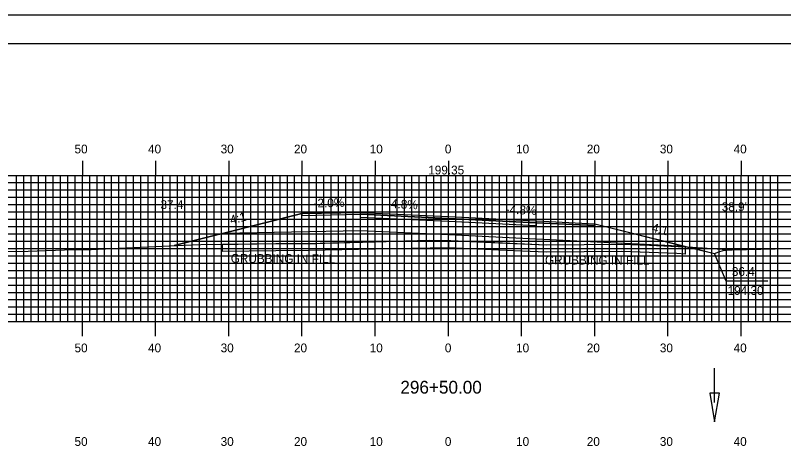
# Model space of a CAD drawing. Extents: x 1814522 to 1814865, y 442591 to 442811.
# Drawn here: x 1814628.4 to 1814733.3, y 442751.2 to 442810.5 of the extents above; entities that cross this region are included whole.
import ezdxf

# ---------------------------------------------------------------- set-up
doc = ezdxf.new("R2010")
doc.units = 0
for name, color, linetype in [('ANNOTATION', 7, 'Continuous'), ('BORDER', 7, 'Continuous'), ('D_Drainage_Ditch_Line', 7, 'Continuous'), ('D_Roadway_Centerline', 7, 'Continuous'), ('D_Roadway_Centerline_Text', 7, 'Continuous'), ('D_Roadway_Edge_Shoulder', 7, 'Continuous'), ('D_Roadway_Edge_TW', 7, 'Continuous'), ('D_Roadway_Pavement', 7, 'Continuous'), ('D_Roadway_SlopeLines', 7, 'Continuous'), ('D_Roadway_SubGrade', 7, 'Continuous'), ('D_Text_Standard', 7, 'Continuous'), ('GRUBBING IN FILL', 7, 'Continuous'), ('H_V ANNOTATION', 7, 'Continuous'), ('MAJOR', 7, 'Continuous'), ('MINOR', 7, 'Continuous'), ('PLOT BOUNDARY', 7, 'Continuous'), ('S_Roadway_Centerline', 7, 'Continuous')]:
    doc.layers.add(name, color=color, linetype=linetype)

msp = doc.modelspace()

# ---------------------------------------------------------------- linework, layer by layer
at = {"layer": 'ANNOTATION'}
msp.add_lwpolyline([(1814731.14, 442774.19), (1814725.44, 442774.19), (1814723.88, 442777.96)], dxfattribs=at)
at = {"layer": 'BORDER'}
msp.add_lwpolyline([(1814537.91, 442596.67), (1814857.91, 442596.67), (1814857.91, 442806.67), (1814537.91, 442806.67)], close=True, dxfattribs=at)
at = {"layer": 'D_Drainage_Ditch_Line'}
msp.add_line((1814723.88, 442757.59), (1814723.88, 442762.29), dxfattribs=at)
msp.add_lwpolyline([(1814724.54, 442758.9), (1814723.23, 442758.9), (1814723.88, 442754.96)], close=True, dxfattribs=at)
at = {"layer": 'D_Roadway_Centerline'}
msp.add_lwpolyline([(1814650.06, 442779.07), (1814655.51, 442780.43), (1814656.64, 442780.71), (1814667.51, 442783.43), (1814675.51, 442783.59), (1814687.51, 442783.02), (1814699.51, 442782.44), (1814707.51, 442782.06), (1814719.88, 442778.96), (1814723.88, 442777.96), (1814724.48, 442778.22), (1814725.07, 442778.39), (1814725.67, 442778.47), (1814726.26, 442778.47)], dxfattribs=at)
at = {"layer": 'D_Roadway_Edge_Shoulder'}
for points in [[(1814675.51, 442783.59), (1814667.51, 442783.43), (1814667.51, 442783.18), (1814675.51, 442783.34)], [(1814699.51, 442782.44), (1814707.51, 442782.06), (1814707.51, 442781.81), (1814699.51, 442782.19)]]:
    msp.add_lwpolyline(points, close=True, dxfattribs=at)
at = {"layer": 'D_Roadway_Edge_TW'}
msp.add_lwpolyline([(1814675.51, 442783.34), (1814675.51, 442783.59), (1814687.51, 442783.02), (1814699.51, 442782.44), (1814699.51, 442782.19), (1814687.51, 442782.77)], close=True, dxfattribs=at)
at = {"layer": 'D_Roadway_Pavement'}
msp.add_lwpolyline([(1814675.51, 442782.92), (1814675.51, 442783.34), (1814687.51, 442782.77), (1814699.51, 442782.19), (1814699.51, 442781.77), (1814687.51, 442782.35)], close=True, dxfattribs=at)
at = {"layer": 'D_Roadway_SlopeLines'}
for points in [[(1814667.51, 442783.43), (1814656.64, 442780.71), (1814655.51, 442780.43), (1814650.06, 442779.07)], [(1814707.51, 442782.06), (1814723.88, 442777.96)], [(1814723.88, 442777.96), (1814724.48, 442778.22), (1814725.07, 442778.39), (1814725.67, 442778.47), (1814726.26, 442778.47)]]:
    msp.add_lwpolyline(points, dxfattribs=at)
at = {"layer": 'D_Roadway_SubGrade'}
msp.add_lwpolyline([(1814675.51, 442781.09), (1814656.64, 442780.71), (1814667.51, 442783.43), (1814667.51, 442783.18), (1814675.51, 442783.34), (1814687.51, 442782.77), (1814699.51, 442782.19), (1814707.51, 442781.81), (1814707.51, 442782.06), (1814719.88, 442778.96), (1814699.51, 442779.94), (1814687.51, 442780.52)], close=True, dxfattribs=at)
at = {"layer": 'GRUBBING IN FILL'}
for points in [[(1814656.64, 442779.25), (1814658.81, 442779.27), (1814663.94, 442779.33), (1814668.89, 442779.37), (1814677.49, 442779.59), (1814684.98, 442779.79), (1814687.51, 442779.75), (1814687.51, 442778.75), (1814677.51, 442778.59), (1814668.41, 442778.37), (1814663.96, 442778.33), (1814656.64, 442778.25)], [(1814656.64, 442779.25), (1814658.81, 442779.27), (1814663.94, 442779.33), (1814668.89, 442779.37), (1814677.49, 442779.59), (1814684.98, 442779.79), (1814687.51, 442779.75), (1814687.51, 442778.75), (1814677.51, 442778.59), (1814668.41, 442778.37), (1814663.96, 442778.33), (1814656.64, 442778.25)], [(1814687.51, 442779.75), (1814694.37, 442779.44), (1814700.91, 442779.15), (1814706.05, 442779.2), (1814711.2, 442779.26), (1814714.99, 442779.12), (1814719.88, 442778.91), (1814719.88, 442777.9), (1814718.73, 442777.98), (1814714.96, 442778.12), (1814711.19, 442778.26), (1814706.04, 442778.2), (1814700.89, 442778.15), (1814694.35, 442778.44), (1814687.51, 442778.75)], [(1814687.51, 442779.75), (1814694.37, 442779.44), (1814700.91, 442779.15), (1814706.05, 442779.2), (1814711.2, 442779.26), (1814714.99, 442779.12), (1814719.88, 442778.91), (1814719.88, 442777.9), (1814718.73, 442777.98), (1814714.96, 442778.12), (1814711.19, 442778.26), (1814706.04, 442778.2), (1814700.89, 442778.15), (1814694.35, 442778.44), (1814687.51, 442778.75)]]:
    msp.add_lwpolyline(points, close=True, dxfattribs=at)
at = {"layer": 'MAJOR'}
for p, q in [((1814637.51, 442790.67), (1814637.51, 442788.67)), ((1814647.51, 442790.67), (1814647.51, 442788.67)), ((1814657.51, 442790.67), (1814657.51, 442788.67)), ((1814667.51, 442790.67), (1814667.51, 442788.67)), ((1814677.51, 442790.67), (1814677.51, 442788.67)), ((1814687.51, 442790.67), (1814687.51, 442788.67)), ((1814697.51, 442790.67), (1814697.51, 442788.67)), ((1814707.51, 442790.67), (1814707.51, 442788.67)), ((1814717.51, 442790.67), (1814717.51, 442788.67)), ((1814727.51, 442790.67), (1814727.51, 442788.67)), ((1814547.51, 442788.67), (1814827.51, 442788.67)), ((1814547.51, 442788.67), (1814827.51, 442788.67)), ((1814637.51, 442768.67), (1814637.51, 442788.67)), ((1814647.51, 442768.67), (1814647.51, 442788.67)), ((1814657.51, 442768.67), (1814657.51, 442788.67)), ((1814667.51, 442768.67), (1814667.51, 442788.67)), ((1814677.51, 442768.67), (1814677.51, 442788.67)), ((1814687.51, 442768.67), (1814687.51, 442788.67)), ((1814697.51, 442768.67), (1814697.51, 442788.67)), ((1814707.51, 442768.67), (1814707.51, 442788.67)), ((1814717.51, 442768.67), (1814717.51, 442788.67)), ((1814727.51, 442768.67), (1814727.51, 442788.67)), ((1814547.51, 442783.67), (1814827.51, 442783.67)), ((1814547.51, 442778.67), (1814827.51, 442778.67)), ((1814547.51, 442773.67), (1814827.51, 442773.67)), ((1814547.51, 442768.67), (1814827.51, 442768.67)), ((1814547.51, 442768.67), (1814827.51, 442768.67)), ((1814637.51, 442766.66), (1814637.51, 442768.67)), ((1814647.51, 442766.66), (1814647.51, 442768.67)), ((1814657.51, 442766.66), (1814657.51, 442768.67)), ((1814667.51, 442766.66), (1814667.51, 442768.67)), ((1814677.51, 442766.66), (1814677.51, 442768.67)), ((1814687.51, 442766.66), (1814687.51, 442768.67)), ((1814697.51, 442766.66), (1814697.51, 442768.67)), ((1814707.51, 442766.66), (1814707.51, 442768.67)), ((1814717.51, 442766.66), (1814717.51, 442768.67)), ((1814727.51, 442766.66), (1814727.51, 442768.67))]:
    msp.add_line(p, q, dxfattribs=at)
at = {"layer": 'MINOR'}
for p, q in [((1814547.51, 442787.67), (1814827.51, 442787.67)), ((1814628.51, 442768.67), (1814628.51, 442788.67)), ((1814629.51, 442768.67), (1814629.51, 442788.67)), ((1814630.51, 442768.67), (1814630.51, 442788.67)), ((1814631.51, 442768.67), (1814631.51, 442788.67)), ((1814632.51, 442768.67), (1814632.51, 442788.67)), ((1814633.51, 442768.67), (1814633.51, 442788.67)), ((1814634.51, 442768.67), (1814634.51, 442788.67)), ((1814635.51, 442768.67), (1814635.51, 442788.67)), ((1814636.51, 442768.67), (1814636.51, 442788.67)), ((1814638.51, 442768.67), (1814638.51, 442788.67)), ((1814639.51, 442768.67), (1814639.51, 442788.67)), ((1814640.51, 442768.67), (1814640.51, 442788.67)), ((1814641.51, 442768.67), (1814641.51, 442788.67)), ((1814642.51, 442768.67), (1814642.51, 442788.67)), ((1814643.51, 442768.67), (1814643.51, 442788.67)), ((1814644.51, 442768.67), (1814644.51, 442788.67)), ((1814645.51, 442768.67), (1814645.51, 442788.67)), ((1814646.51, 442768.67), (1814646.51, 442788.67)), ((1814648.51, 442768.67), (1814648.51, 442788.67)), ((1814649.51, 442768.67), (1814649.51, 442788.67)), ((1814650.51, 442768.67), (1814650.51, 442788.67)), ((1814651.51, 442768.67), (1814651.51, 442788.67)), ((1814652.51, 442768.67), (1814652.51, 442788.67)), ((1814653.51, 442768.67), (1814653.51, 442788.67)), ((1814654.51, 442768.67), (1814654.51, 442788.67)), ((1814655.51, 442768.67), (1814655.51, 442788.67)), ((1814656.51, 442768.67), (1814656.51, 442788.67)), ((1814658.51, 442768.67), (1814658.51, 442788.67)), ((1814659.51, 442768.67), (1814659.51, 442788.67)), ((1814660.51, 442768.67), (1814660.51, 442788.67)), ((1814661.51, 442768.67), (1814661.51, 442788.67)), ((1814662.51, 442768.67), (1814662.51, 442788.67)), ((1814663.51, 442768.67), (1814663.51, 442788.67)), ((1814664.51, 442768.67), (1814664.51, 442788.67)), ((1814665.51, 442768.67), (1814665.51, 442788.67)), ((1814666.51, 442768.67), (1814666.51, 442788.67)), ((1814668.51, 442768.67), (1814668.51, 442788.67)), ((1814669.51, 442768.67), (1814669.51, 442788.67)), ((1814670.51, 442768.67), (1814670.51, 442788.67)), ((1814671.51, 442768.67), (1814671.51, 442788.67)), ((1814672.51, 442768.67), (1814672.51, 442788.67)), ((1814673.51, 442768.67), (1814673.51, 442788.67)), ((1814674.51, 442768.67), (1814674.51, 442788.67)), ((1814675.51, 442768.67), (1814675.51, 442788.67)), ((1814676.51, 442768.67), (1814676.51, 442788.67)), ((1814678.51, 442768.67), (1814678.51, 442788.67)), ((1814679.51, 442768.67), (1814679.51, 442788.67)), ((1814680.51, 442768.67), (1814680.51, 442788.67)), ((1814681.51, 442768.67), (1814681.51, 442788.67)), ((1814682.51, 442768.67), (1814682.51, 442788.67)), ((1814683.51, 442768.67), (1814683.51, 442788.67)), ((1814684.51, 442768.67), (1814684.51, 442788.67)), ((1814685.51, 442768.67), (1814685.51, 442788.67)), ((1814686.51, 442768.67), (1814686.51, 442788.67)), ((1814688.51, 442768.67), (1814688.51, 442788.67)), ((1814689.51, 442768.67), (1814689.51, 442788.67)), ((1814690.51, 442768.67), (1814690.51, 442788.67)), ((1814691.51, 442768.67), (1814691.51, 442788.67)), ((1814692.51, 442768.67), (1814692.51, 442788.67)), ((1814693.51, 442768.67), (1814693.51, 442788.67)), ((1814694.51, 442768.67), (1814694.51, 442788.67)), ((1814695.51, 442768.67), (1814695.51, 442788.67)), ((1814696.51, 442768.67), (1814696.51, 442788.67)), ((1814698.51, 442768.67), (1814698.51, 442788.67)), ((1814699.51, 442768.67), (1814699.51, 442788.67)), ((1814700.51, 442768.67), (1814700.51, 442788.67)), ((1814701.51, 442768.67), (1814701.51, 442788.67)), ((1814702.51, 442768.67), (1814702.51, 442788.67)), ((1814703.51, 442768.67), (1814703.51, 442788.67)), ((1814704.51, 442768.67), (1814704.51, 442788.67)), ((1814705.51, 442768.67), (1814705.51, 442788.67)), ((1814706.51, 442768.67), (1814706.51, 442788.67)), ((1814708.51, 442768.67), (1814708.51, 442788.67)), ((1814709.51, 442768.67), (1814709.51, 442788.67)), ((1814710.51, 442768.67), (1814710.51, 442788.67)), ((1814711.51, 442768.67), (1814711.51, 442788.67)), ((1814712.51, 442768.67), (1814712.51, 442788.67)), ((1814713.51, 442768.67), (1814713.51, 442788.67)), ((1814714.51, 442768.67), (1814714.51, 442788.67)), ((1814715.51, 442768.67), (1814715.51, 442788.67)), ((1814716.51, 442768.67), (1814716.51, 442788.67)), ((1814718.51, 442768.67), (1814718.51, 442788.67)), ((1814719.51, 442768.67), (1814719.51, 442788.67)), ((1814720.51, 442768.67), (1814720.51, 442788.67)), ((1814721.51, 442768.67), (1814721.51, 442788.67)), ((1814722.51, 442768.67), (1814722.51, 442788.67)), ((1814723.51, 442768.67), (1814723.51, 442788.67)), ((1814724.51, 442768.67), (1814724.51, 442788.67)), ((1814725.51, 442768.67), (1814725.51, 442788.67)), ((1814726.51, 442768.67), (1814726.51, 442788.67)), ((1814728.51, 442768.67), (1814728.51, 442788.67)), ((1814729.51, 442768.67), (1814729.51, 442788.67)), ((1814730.51, 442768.67), (1814730.51, 442788.67)), ((1814731.51, 442768.67), (1814731.51, 442788.67)), ((1814732.51, 442768.67), (1814732.51, 442788.67)), ((1814547.51, 442786.67), (1814827.51, 442786.67)), ((1814547.51, 442785.67), (1814827.51, 442785.67)), ((1814547.51, 442784.67), (1814827.51, 442784.67)), ((1814547.51, 442782.67), (1814827.51, 442782.67)), ((1814547.51, 442781.67), (1814827.51, 442781.67)), ((1814547.51, 442780.67), (1814827.51, 442780.67)), ((1814547.51, 442779.67), (1814827.51, 442779.67)), ((1814547.51, 442777.67), (1814827.51, 442777.67)), ((1814547.51, 442776.67), (1814827.51, 442776.67)), ((1814547.51, 442775.67), (1814827.51, 442775.67)), ((1814547.51, 442774.67), (1814827.51, 442774.67)), ((1814547.51, 442772.67), (1814827.51, 442772.67)), ((1814547.51, 442771.67), (1814827.51, 442771.67)), ((1814547.51, 442770.67), (1814827.51, 442770.67)), ((1814547.51, 442769.67), (1814827.51, 442769.67))]:
    msp.add_line(p, q, dxfattribs=at)
at = {"layer": 'PLOT BOUNDARY'}
msp.add_lwpolyline([(1814521.72, 442590.55), (1814861.72, 442590.55), (1814861.72, 442810.55), (1814521.72, 442810.55)], close=True, dxfattribs=at)
at = {"layer": 'S_Roadway_Centerline'}
msp.add_lwpolyline([(1814618.49, 442778.17), (1814630.09, 442778.31), (1814635.06, 442778.46), (1814638.73, 442778.53), (1814651.33, 442779.13), (1814653.68, 442779.21), (1814663.94, 442779.33), (1814668.4, 442779.37), (1814669.38, 442779.37), (1814670.01, 442779.39), (1814684.98, 442779.79), (1814687.83, 442779.74), (1814700.91, 442779.15), (1814711.2, 442779.26), (1814718.79, 442778.98), (1814726.3, 442778.47), (1814734.13, 442778.67)], dxfattribs=at)

# ---------------------------------------------------------------- texts
at = {"layer": 'ANNOTATION'}
for s, rotation, p in [('-2.0%', 1.1458, (1814669.11, 442784.26)), ('4.8%', 357.2519, (1814679.64, 442784.2)), ('-4.8%', 357.2519, (1814695.32, 442783.44)), ('4:1', 14.0362, (1814657.83, 442781.96)), ('4:1', 345.9638, (1814715.2, 442780.99))]:
    msp.add_text(s, height=1.2, rotation=rotation, dxfattribs=at).set_placement(p)
for s, p in [("36.4'", (1814726.24, 442774.92)), ('194.30', (1814725.66, 442772.32))]:
    msp.add_text(s, height=1.2, dxfattribs=at).set_placement(p)
at = {"layer": 'D_Roadway_Centerline'}
for s, p in [('C', (1814687.5, 442783.02)), ('L', (1814687.51, 442783.01))]:
    msp.add_text(s, height=0.0146, dxfattribs=at).set_placement(p)
at = {"layer": 'D_Roadway_Centerline_Text'}
msp.add_text('199.35', height=1.2, dxfattribs=at).set_placement((1814684.76, 442788.79))
at = {"layer": 'D_Text_Standard'}
for s, p in [("37.4'", (1814648.18, 442784.06)), ("38.9'", (1814724.85, 442783.77))]:
    msp.add_text(s, height=1.2, dxfattribs=at).set_placement(p)
at = {"layer": 'GRUBBING IN FILL'}
for p in [(1814657.78, 442776.71), (1814700.71, 442776.49)]:
    msp.add_text('GRUBBING IN FILL', height=1.2, rotation=359.8053, dxfattribs=at).set_placement(p)
at = {"layer": 'H_V ANNOTATION'}
for s, height, p in [('50', 1.2, (1814636.44, 442791.67)), ('40', 1.2, (1814646.48, 442791.67)), ('30', 1.2, (1814656.4, 442791.67)), ('20', 1.2, (1814666.42, 442791.67)), ('10', 1.2, (1814676.76, 442791.67)), ('0', 1.2, (1814687.03, 442791.67)), ('10', 1.2, (1814696.76, 442791.67)), ('20', 1.2, (1814706.42, 442791.67)), ('30', 1.2, (1814716.4, 442791.67)), ('40', 1.2, (1814726.48, 442791.67)), ('50', 1.2, (1814636.44, 442764.47)), ('40', 1.2, (1814646.48, 442764.47)), ('30', 1.2, (1814656.4, 442764.47)), ('20', 1.2, (1814666.42, 442764.47)), ('10', 1.2, (1814676.76, 442764.47)), ('0', 1.2, (1814687.03, 442764.47)), ('10', 1.2, (1814696.76, 442764.47)), ('20', 1.2, (1814706.42, 442764.47)), ('30', 1.2, (1814716.4, 442764.47)), ('40', 1.2, (1814726.48, 442764.47)), ('296+50.00', 1.75, (1814680.95, 442758.82)), ('50', 1.2, (1814636.44, 442751.67)), ('40', 1.2, (1814646.48, 442751.67)), ('30', 1.2, (1814656.4, 442751.67)), ('20', 1.2, (1814666.42, 442751.67)), ('10', 1.2, (1814676.76, 442751.67)), ('0', 1.2, (1814687.03, 442751.67)), ('10', 1.2, (1814696.76, 442751.67)), ('20', 1.2, (1814706.42, 442751.67)), ('30', 1.2, (1814716.4, 442751.67)), ('40', 1.2, (1814726.48, 442751.67))]:
    msp.add_text(s, height=height, dxfattribs=at).set_placement(p)

doc.saveas('drawing.dxf')
